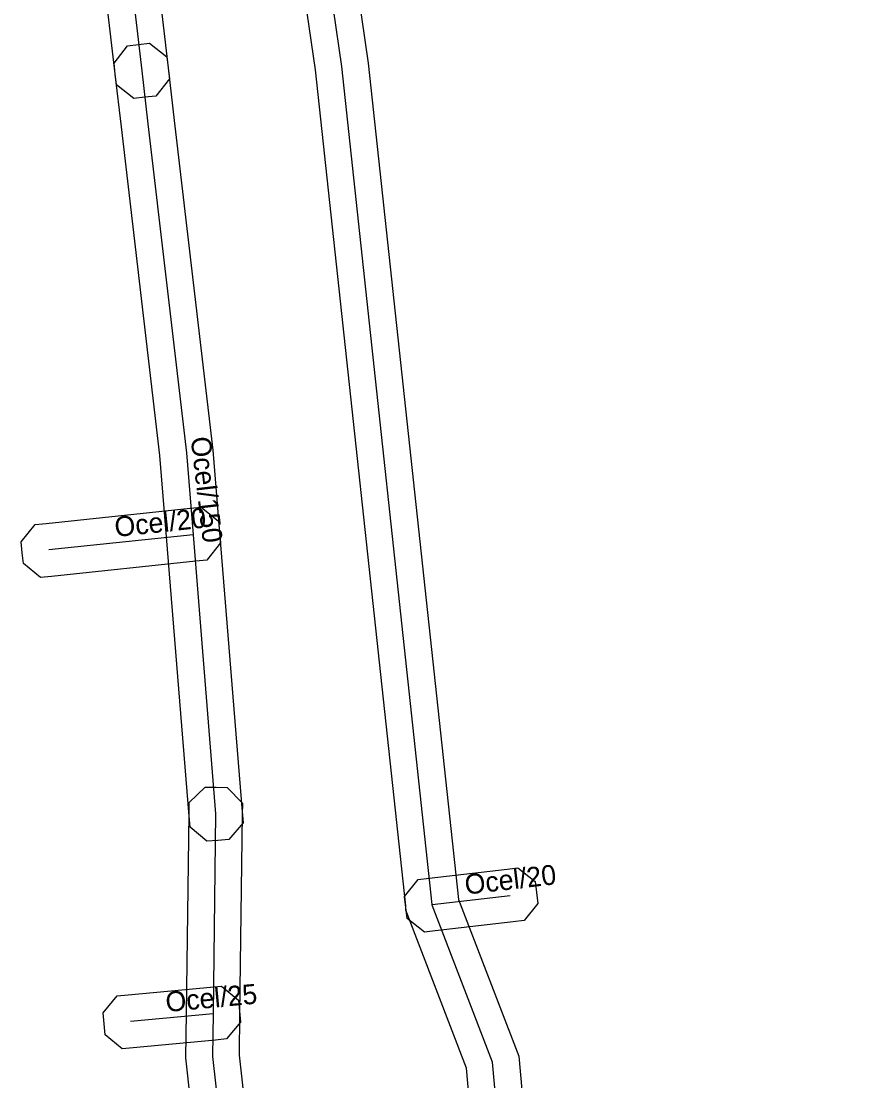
# Model space of a CAD drawing. Extents: x -569373 to -565022, y -1135090 to -1131496.
# Drawn here: x -565664.14 to -565632.13, y -1133335.9 to -1133296.04 of the extents above; entities that cross this region are included whole.
import ezdxf

# ---------------------------------------------------------------- set-up
doc = ezdxf.new("R2010")
doc.units = 0
for name, color, linetype in [('1', 7, 'Continuous'), ('24', 7, 'Continuous'), ('30', 7, 'Continuous')]:
    doc.layers.add(name, color=color, linetype=linetype)

msp = doc.modelspace()

# ---------------------------------------------------------------- linework, layer by layer
at = {"layer": '1'}
for points in [[(-565646.525, -1133345.02), (-565647.384, -1133335.429), (-565649.67, -1133329.486), (-565649.67, -1133329.321), (-565653.062, -1133297.866), (-565653.689, -1133293.565), (-565654.495, -1133288.118), (-565653.151, -1133285.389), (-565653.17, -1133280.304), (-565653.172, -1133279.89), (-565652.588, -1133279.302), (-565652.174, -1133279.3), (-565651.76, -1133279.298), (-565651.172, -1133279.882), (-565651.17, -1133280.296), (-565651.149, -1133285.851), (-565652.425, -1133288.442), (-565651.711, -1133293.275), (-565651.078, -1133297.614), (-565647.685, -1133329.076), (-565645.416, -1133334.971), (-565644.535, -1133344.82)], [(-565657.574, -1133338.331), (-565657.941, -1133335.039), (-565657.92, -1133333.357), (-565657.82, -1133325.847), (-565657.815, -1133325.433), (-565657.221, -1133324.855), (-565656.807, -1133324.86), (-565656.393, -1133324.865), (-565655.815, -1133325.459), (-565655.82, -1133325.873), (-565655.92, -1133333.383), (-565655.939, -1133334.941), (-565655.586, -1133338.109)]]:
    msp.add_lwpolyline(points, dxfattribs=at)
for points in [[(-565660.439, -1133282.186), (-565660.391, -1133282.598), (-565658.611, -1133297.794), (-565658.563, -1133298.205), (-565659.076, -1133298.855), (-565659.488, -1133298.903), (-565659.899, -1133298.951), (-565660.549, -1133298.438), (-565660.597, -1133298.026), (-565662.377, -1133282.83), (-565662.425, -1133282.419), (-565661.912, -1133281.769), (-565661.5, -1133281.721), (-565661.089, -1133281.673)], [(-565658.659, -1133297.382), (-565658.611, -1133297.793), (-565658.378, -1133299.78), (-565656.925, -1133312.181), (-565656.673, -1133315.279), (-565655.823, -1133325.779), (-565655.79, -1133326.192), (-565656.326, -1133326.823), (-565656.739, -1133326.857), (-565657.152, -1133326.89), (-565657.783, -1133326.354), (-565657.817, -1133325.941), (-565658.667, -1133315.441), (-565658.915, -1133312.379), (-565660.364, -1133300.012), (-565660.597, -1133298.027), (-565660.645, -1133297.615), (-565660.132, -1133296.965), (-565659.721, -1133296.917), (-565659.309, -1133296.869)], [(-565657.154, -1133316.312), (-565657.566, -1133316.355), (-565662.996, -1133316.925), (-565663.408, -1133316.968), (-565664.052, -1133316.446), (-565664.095, -1133316.034), (-565664.138, -1133315.622), (-565663.616, -1133314.978), (-565663.204, -1133314.935), (-565657.774, -1133314.365), (-565657.362, -1133314.322), (-565656.718, -1133314.844), (-565656.675, -1133315.256), (-565656.632, -1133315.668)], [(-565649.197, -1133328.325), (-565648.785, -1133328.277), (-565645.855, -1133327.937), (-565645.444, -1133327.889), (-565644.795, -1133328.403), (-565644.747, -1133328.815), (-565644.699, -1133329.226), (-565645.213, -1133329.875), (-565645.625, -1133329.923), (-565648.555, -1133330.263), (-565648.966, -1133330.311), (-565649.615, -1133329.797), (-565649.663, -1133329.385), (-565649.711, -1133328.974)], [(-565660.526, -1133332.703), (-565660.113, -1133332.664), (-565657.013, -1133332.374), (-565656.6, -1133332.335), (-565655.963, -1133332.864), (-565655.924, -1133333.277), (-565655.885, -1133333.69), (-565656.414, -1133334.327), (-565656.827, -1133334.366), (-565659.927, -1133334.656), (-565660.34, -1133334.695), (-565660.977, -1133334.166), (-565661.016, -1133333.753), (-565661.055, -1133333.34)]]:
    msp.add_lwpolyline(points, close=True, dxfattribs=at)
at = {"layer": '24'}
for points in [[(-565632.13, -1133459.49), (-565635.18, -1133435.22), (-565636.392, -1133425.015), (-565638.801, -1133404.72), (-565639.7, -1133397.15), (-565643.15, -1133366.24), (-565644.64, -1133352.93), (-565645.53, -1133344.92), (-565646.4, -1133335.2), (-565648.67, -1133329.3), (-565648.67, -1133329.27), (-565652.07, -1133297.74), (-565652.7, -1133293.42), (-565653.46, -1133288.28), (-565652.15, -1133285.62), (-565652.17, -1133280.3)], [(-565661.384, -1133282.714), (-565659.604, -1133297.91)], [(-565659.604, -1133297.91), (-565659.371, -1133299.896), (-565657.92, -1133312.28), (-565657.67, -1133315.36), (-565656.82, -1133325.86)], [(-565657.67, -1133315.36), (-565663.1, -1133315.93)], [(-565656.82, -1133325.86), (-565656.92, -1133333.37), (-565656.94, -1133334.99), (-565656.58, -1133338.22), (-565653.69, -1133364.1), (-565653.18, -1133368.61), (-565651.02, -1133387.94), (-565650.91, -1133389.12), (-565648.81, -1133412.08), (-565648.19, -1133418.69), (-565646.37, -1133438.06), (-565643.28, -1133468)], [(-565648.67, -1133329.27), (-565645.74, -1133328.93)], [(-565660.02, -1133333.66), (-565656.92, -1133333.37)]]:
    msp.add_lwpolyline(points, dxfattribs=at)

# ---------------------------------------------------------------- texts
at = {"layer": '30'}
for s, rotation, p in [('Ocel/150', 276.6827, (-565657.763, -1133311.711)), ('Ocel/20', 5.9925, (-565660.585, -1133315.445)), ('Ocel/20', 6.6191, (-565647.405, -1133328.9)), ('Ocel/25', 5.3444, (-565658.67, -1133333.315))]:
    msp.add_text(s, height=0.75, rotation=rotation, dxfattribs=at).set_placement(p)

doc.saveas('drawing.dxf')
